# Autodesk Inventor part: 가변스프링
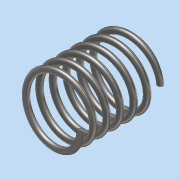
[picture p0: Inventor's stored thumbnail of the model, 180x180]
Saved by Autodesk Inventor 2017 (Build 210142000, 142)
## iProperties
Part Number: 가변스프링
Material: 스테인레스 스틸
Document SubType Name: Modeling
Designer: 7-1
Density: 8 g/cm^3
Appearance: 반연마
Mass: 9.32453 g
Surface Area: 23.6146 cm^2
Volume: 1.16557 cm^3
Author: 7-1
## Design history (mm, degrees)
sketch "스케치1"
  geometry: L1 (0, 0)-(0, 26.7); L2 (0, 26.7)-(39.861, 26.7); C1 r 1 at (10, 0)
  constraints: 4 end point, 1 centre point, 1 horizontal alignment, 1 perpendicular, 1 vertical
  dimensions: "d0" = 26.7 distance of L1.start L1.end (derived); "d1" = 2 diameter of C1; "d2" = 20 diameter of C1.centre L1
feature "코일1" sketch "스케치1" pitch "d3" = 10; turns "d5" = 6; dims "d4" = 26.7 (= d0), "d6" = 0, angle "d7" = 90 deg, angle "d8" = 90 deg, "d9" = 0, "d10" = 0
sketch "스케치2"
  geometry: L1 (0, 13.611)-(26.7, 13.611); L2 (26.7, 13.611)-(26.7, -13.611); L3 (26.7, -13.611)-(0, -13.611); L4 (0, -13.611)-(0, 13.611); 2 further points
  constraints: 8 end point, 2 parallel, 1 coincident, 1 horizontal, 1 midpoint, 1 perpendicular
  dimensions: "d11" = 26.7 distance of L2.end L3.end (derived); "d12" = 27.22222 distance of L1.end L2.end
extrude "돌출1" sketch "스케치2" stored distance "d13" = 10; taper "d14" = 0 deg
node "솔리드1"
